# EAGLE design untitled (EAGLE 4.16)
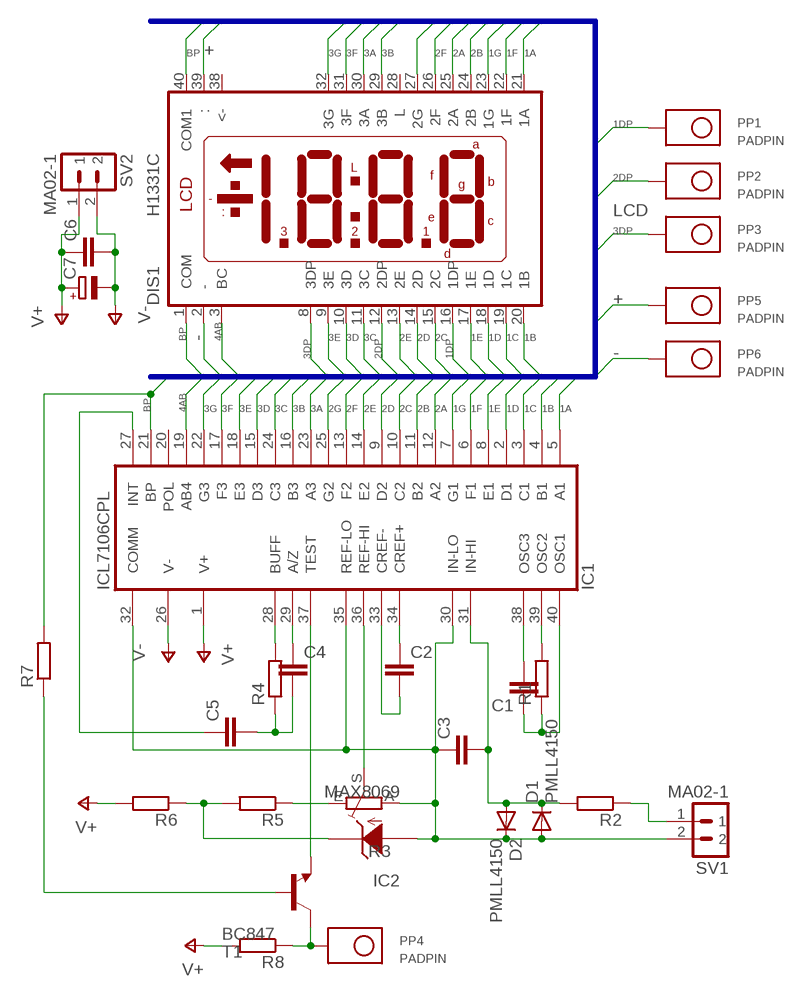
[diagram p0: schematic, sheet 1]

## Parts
C1  C-EUC1210  [C1210]
C2  C-EUC1210  [C1210]
C3  C-EUC1210  [C1210]
C4  C-EUC1210  [C1210]
C5  C-EUC1210  [C1210]
C6  C-EUC1210  [C1210]
C7  CPOL-EUE2.5-5  [E2,5-5]
D1  PMLL4150  [SOD80C]
D2  PMLL4150  [SOD80C]
DIS1  H1331C  [H1331C]
IC1  ICL7106CPL  [DIL40]
IC2  MAX8069  [TO92-2]
PP1  PADPIN  [PAD]
PP2  PADPIN  [PAD]
PP3  PADPIN  [PAD]
PP4  PADPIN  [PAD]
PP5  PADPIN  [PAD]
PP6  PADPIN  [PAD]
R1  R-EU_M1206  [M1206]
R2  R-EU_M1206  [M1206]
R3  TRIM_EU-B90P  [SP19L]
R4  R-EU_M1206  [M1206]
R5  R-EU_M1206  [M1206]
R6  R-EU_M1206  [M1206]
R7  R-EU_M1206  [M1206]
R8  R-EU_M1206  [M1206]
SV1  MA02-1  [MA02-1]
SV2  MA02-1  [MA02-1]
T1  BC847  [SOT23]

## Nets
1A: DIS1.21(1A) IC1.5(A1)
1B: DIS1.20(1B) IC1.4(B1)
1C: DIS1.19(1C) IC1.3(C1)
1D: DIS1.18(1D) IC1.2(D1)
1DP: DIS1.16(1DP) PP1.P$1
1E: DIS1.17(1E) IC1.8(E1)
1F: DIS1.22(1F) IC1.6(F1)
1G: DIS1.23(1G) IC1.7(G1)
2A: DIS1.25(2A) IC1.12(A2)
2B: DIS1.24(2B) IC1.11(B2)
2C: DIS1.15(2C) IC1.10(C2)
2D: DIS1.14(2D) IC1.9(D2)
2DP: DIS1.12(2DP) PP2.P$1
2E: DIS1.13(2E) IC1.14(E2)
2F: DIS1.26(2F) IC1.13(F2)
2G: DIS1.27(2G) IC1.25(G2)
3A: DIS1.30(3A) IC1.23(A3)
3B: DIS1.29(3B) IC1.16(B3)
3C: DIS1.11(3C) IC1.24(C3)
3D: DIS1.10(3D) IC1.15(D3)
3DP: DIS1.8(3DP) PP3.P$1
3E: DIS1.9(3E) IC1.18(E3)
3F: DIS1.31(3F) IC1.17(F3)
3G: DIS1.32(3G) IC1.22(G3)
4AB: DIS1.3(BC) IC1.19(AB4)
+: DIS1.39(:) PP5.P$1
-: DIS1.2(-) PP6.P$1
BP: DIS1.1(COM) DIS1.40(COM1) IC1.21(BP) R7.2
N$1: IC1.39(OSC2) R1.2
N$2: C1.2 IC1.38(OSC3)
N$3: C1.1 IC1.40(OSC1) R1.1
N$4: C3.2 D1.C D2.A IC1.31(IN-HI) R2.2
N$5: IC1.36(REF-HI) R3.S
N$6: R2.1 SV1.1
N$7: C2.2 IC1.33(CREF-)
N$8: C2.1 IC1.34(CREF+)
N$9: C3.1 D1.A D2.C IC1.30(IN-LO) IC1.32(COMM) IC1.35(REF-LO) IC2.A R3.A SV1.2
N$10: C4.1 IC1.29(A/Z)
N$11: IC1.28(BUFF) R4.2
N$12: C5.1 IC1.27(INT)
N$13: C4.2 C5.2 R4.1
N$14: R3.E R5.1
N$15: IC2.K R5.2 R6.1
N$16: R7.1 T1.1(B)
N$17: IC1.37(TEST) T1.2(E)
N$18: PP4.P$1 R8.1 T1.3(C)
V+: C6.1 C7.+ IC1.1(V+) R6.2 R8.2 SV2.1
V-: C6.2 C7.- IC1.26(V-) SV2.2
Unconnected: DIS1.28(L) DIS1.38(<-) IC1.20(POL)

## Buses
LCD

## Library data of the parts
C1-C6 = rcl:C-EU: CAPACITOR, European symbol
C7 = rcl:CPOL-EU: POLARIZED CAPACITOR, European symbol
D1 D2 = diode:PMLL4150: DIODE
DIS1 = display-lcd:H1331C: LCD DISPLAY 3 1/2 character 7 segment
IC1 = maxim:ICL7106CPL: LCD DRIVER
IC2 = max8069:MAX8069
PP1-PP6 = pady:PADPIN
R1 R2 R4-R8 = rcl:R-EU_: RESISTOR, European symbol
R3 = pot:TRIM_EU-: POTENTIOMETER
SV1 SV2 = divers:MA02-1: PIN HEADER
T1 = transistor:BC847: NPN TRANSISTOR

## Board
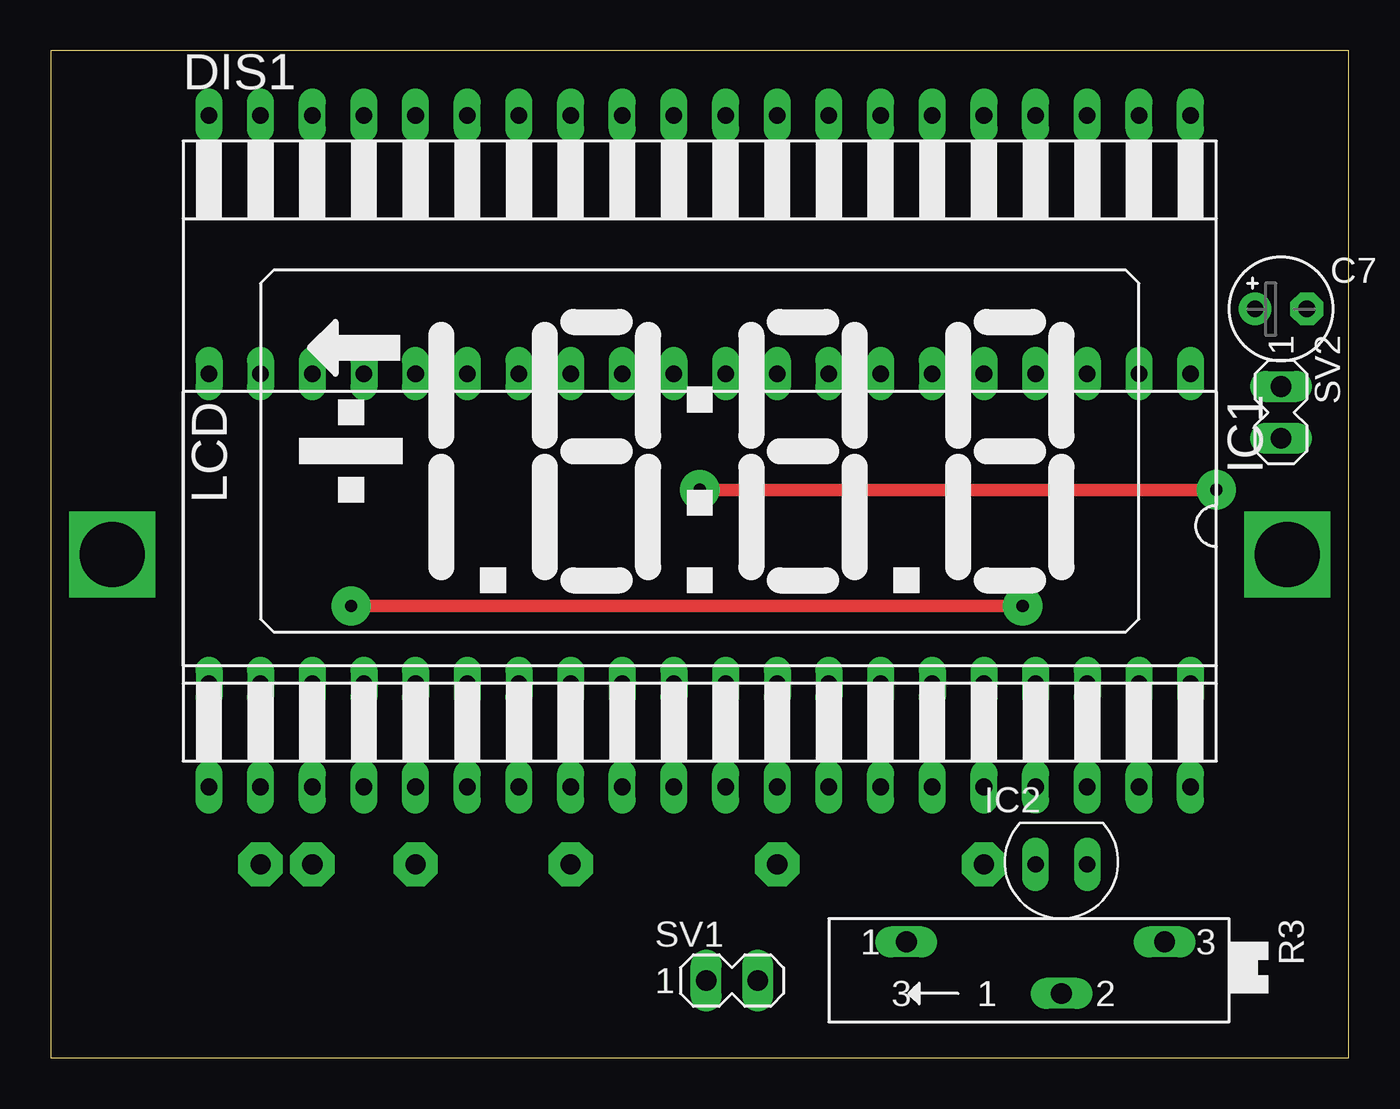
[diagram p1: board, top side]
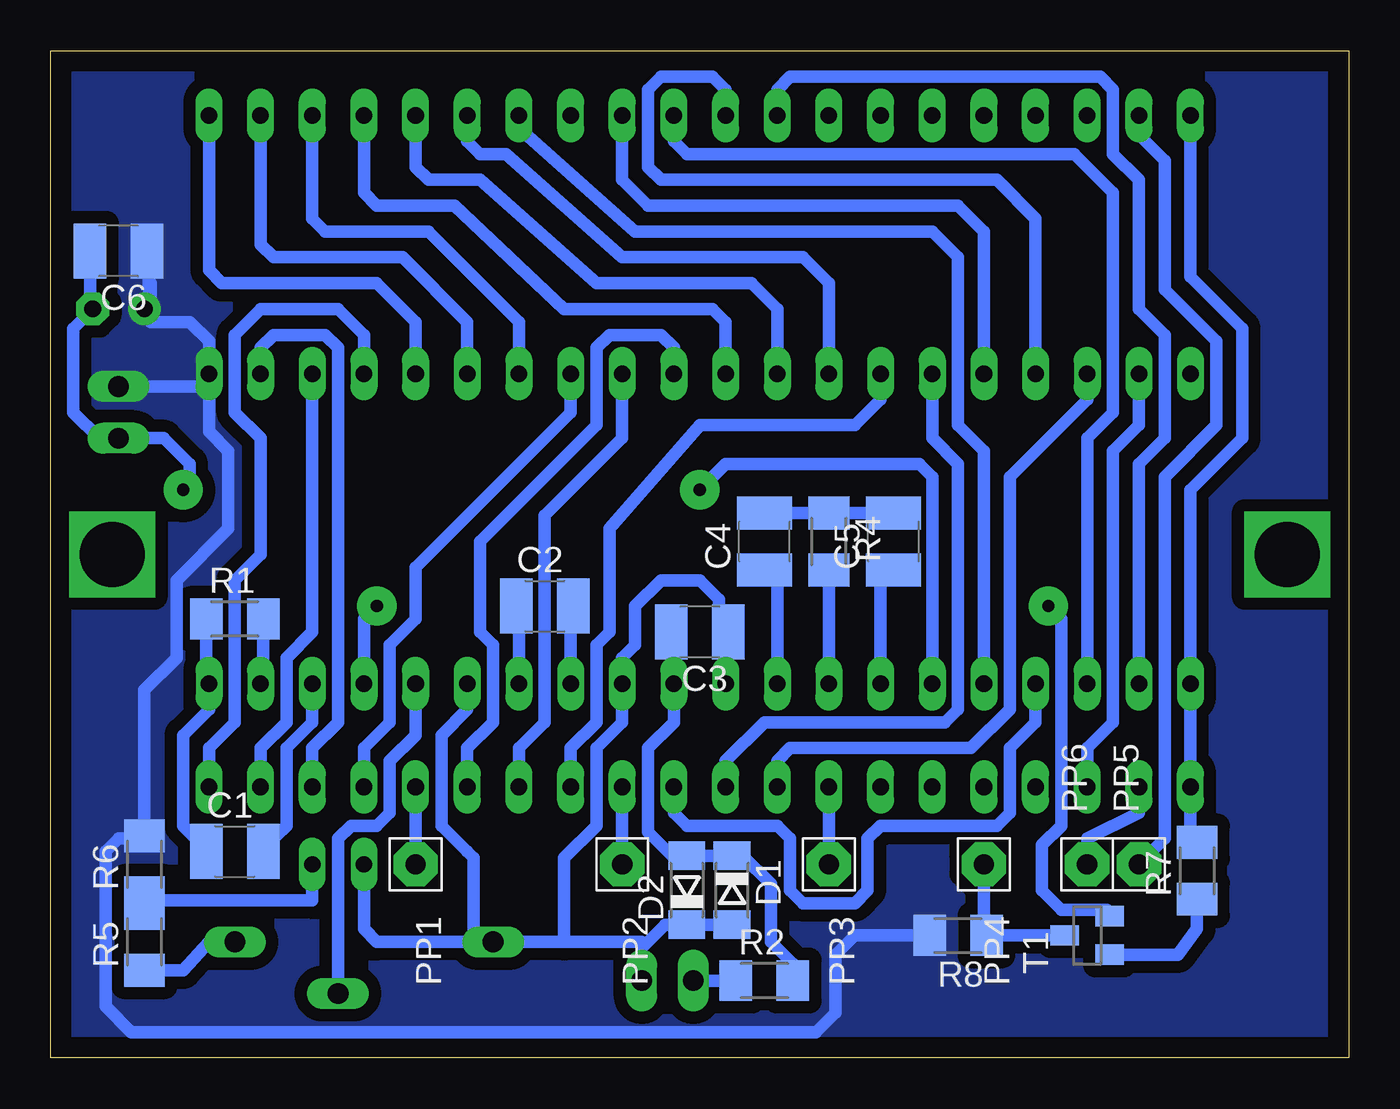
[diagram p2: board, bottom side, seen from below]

Size 63.8 x 49.52 mm. Coordinates in mm from the lower left corner, seen from the top.
Outline: 0,0 63.8,0 63.8,49.52 0,49.52 0,0
Copper layers (1*16): Top 0.035mm / dielectric 1.5mm / Bottom 0.035mm
Design rules "default": minimum track width 10mil, minimum drill 24mil, track to track 8mil, track to pad 8mil, pad to pad 8mil, via to via 8mil, smd to smd 8mil, copper to edge 40mil, drill to drill 8mil, minimum pad ring 10mil, minimum via ring 8mil, stop-mask expansion 4mil, vias tented up to drill 0mil, thermal gap 10mil

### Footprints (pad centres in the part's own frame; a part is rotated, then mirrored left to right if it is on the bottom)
C1210 = smd 1.6 x 2.7: 1 -1.4,0; 2 1.4,0
E2,5-5 = drill 0.813 pad 1.6 round: + -1.27,0 | drill 0.813 pad 1.6 octagon: - 1.27,0
SOD80C = smd 1.4 x 1.8: A 1.7,0; C -1.7,0
H1331C = drill 0.813 long: 1 -24.13,-16.51; 2 -21.59,-16.51; 3 -19.05,-16.51; 4 -16.51,-16.51; 5 -13.97,-16.51; 6 -11.43,-16.51; 7 -8.89,-16.51; 8 -6.35,-16.51; 9 -3.81,-16.51; 10 -1.27,-16.51; 11 1.27,-16.51; 12 3.81,-16.51; 13 6.35,-16.51; 14 8.89,-16.51; 15 11.43,-16.51; 16 13.97,-16.51; 17 16.51,-16.51; 18 19.05,-16.51; 19 21.59,-16.51; 20 24.13,-16.51; 21 24.13,16.51; 22 21.59,16.51; 23 19.05,16.51; 24 16.51,16.51; 25 13.97,16.51; 26 11.43,16.51; 27 8.89,16.51; 28 6.35,16.51; 29 3.81,16.51; 30 1.27,16.51; 31 -1.27,16.51; 32 -3.81,16.51; 33 -6.35,16.51; 34 -8.89,16.51; 35 -11.43,16.51; 36 -13.97,16.51; 37 -16.51,16.51; 38 -19.05,16.51; 39 -21.59,16.51; 40 -24.13,16.51
DIL40 = drill 0.813 long: 1 -24.13,-7.62; 2 -21.59,-7.62; 3 -19.05,-7.62; 4 -16.51,-7.62; 5 -13.97,-7.62; 6 -11.43,-7.62; 7 -8.89,-7.62; 8 -6.35,-7.62; 9 -3.81,-7.62; 10 -1.27,-7.62; 11 1.27,-7.62; 12 3.81,-7.62; 13 6.35,-7.62; 14 8.89,-7.62; 15 11.43,-7.62; 16 13.97,-7.62; 17 16.51,-7.62; 18 19.05,-7.62; 19 21.59,-7.62; 20 24.13,-7.62; 21 24.13,7.62; 22 21.59,7.62; 23 19.05,7.62; 24 16.51,7.62; 25 13.97,7.62; 26 11.43,7.62; 27 8.89,7.62; 28 6.35,7.62; 29 3.81,7.62; 30 1.27,7.62; 31 -1.27,7.62; 32 -3.81,7.62; 33 -6.35,7.62; 34 -8.89,7.62; 35 -11.43,7.62; 36 -13.97,7.62; 37 -16.51,7.62; 38 -19.05,7.62; 39 -21.59,7.62; 40 -24.13,7.62
TO92-2 = drill 0.8 long: A 0,0; K 0,2.54
PAD = drill 1 pad 2.184 octagon: P$1 0,0
M1206 = smd 1.6 x 2: 1 -1.4,0; 2 1.4,0
SP19L = drill 1.016 long: A 5.715,-1.27; E -6.985,-1.27; S -1.905,1.27
MA02-1 = drill 1.016 long: 1 -2.54,0; 2 0,0
SOT23 = smd 1 x 1.4: 1 -0.95,-1.1; 2 0.95,-1.1; 3 0,1.1

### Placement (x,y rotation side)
C1  54.76,10.15 0 bottom
C2  39.52,22.22 0 bottom
C3  31.9,20.95 180 bottom
C4  28.73,25.39 90 bottom
C5  22.38,25.39 90 bottom
C6  60.48,39.68 180 bottom
C7  60.48,36.82 0 top
D1  30.31,8.25 270 bottom
D2  32.54,8.25 90 bottom
DIS1  31.9,29.84 0 top
IC1  31.9,26.03 180 top
IC2  48.41,9.52 270 top
PP1  45.87,9.52 180 bottom
PP2  35.71,9.52 180 bottom
PP3  25.55,9.52 180 bottom
PP4  17.93,9.52 180 bottom
PP5  10.31,9.52 0 bottom
PP6  12.85,9.52 0 bottom
R1  54.76,21.59 0 bottom
R2  28.73,3.8 0 bottom
R3  47.78,4.44 180 top
R4  25.55,25.39 270 bottom
R5  59.21,5.71 90 bottom
R6  59.21,9.52 90 bottom
R7  7.46,9.2 90 bottom
R8  19.2,6.03 180 bottom
SV1  34.76,3.8 0 top
SV2  60.48,30.47 270 top
T1  12.85,6.03 90 bottom

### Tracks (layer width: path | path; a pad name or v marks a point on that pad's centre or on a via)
1A
  Bottom 0.61: IC1.5 45.87,36.19 47.78,38.09 55.4,38.09 56.03,38.73 DIS1.21
1B
  Bottom 0.61: IC1.4 48.41,35.55 49.68,36.82 53.49,36.82 54.76,35.55 54.76,31.74 53.49,30.47 53.49,24.76 54.76,23.49 54.76,16.51 56.03,15.24 DIS1.20
1C
  Bottom 0.61: IC1.3 50.95,20.95 52.22,19.68 52.22,16.51 53.49,15.24 DIS1.19
1D
  Bottom 0.61: DIS1.18 50.95,15.24 49.68,16.51 49.68,34.92 50.32,35.55 52.86,35.55 53.49,34.92 IC1.2
1DP
  Bottom 0.61: PP1.P$1 DIS1.16
1E
  Bottom 0.61: IC1.8 38.25,31.74 45.87,24.12 45.87,21.59 47.14,20.31 47.14,16.51 48.41,15.24 DIS1.17
1F
  Bottom 0.61: IC1.6 43.33,36.19 46.51,39.36 52.86,39.36 53.49,40 DIS1.22
1G
  Bottom 0.61: IC1.7 40.79,36.19 45.24,40.63 50.32,40.63 50.95,41.27 DIS1.23
2A
  Bottom 0.61: IC1.12 28.09,36.82 29.36,38.09 36.98,38.09 42.7,43.17 45.24,43.17 45.87,43.81 DIS1.25
2B
  Bottom 0.61: IC1.11 30.63,36.19 31.27,36.82 38.57,36.82 43.97,41.91 47.78,41.91 48.41,42.54 DIS1.24
2C
  Bottom 0.61: IC1.10 33.17,34.92 33.81,35.55 36.35,35.55 36.98,34.92 36.98,31.11 42.7,25.39 42.7,20.95 42.06,20.31 42.06,16.51 43.33,15.24 DIS1.15
2D
  Bottom 0.61: IC1.9 35.71,30.47 39.52,26.66 39.52,16.51 40.79,15.24 DIS1.14
2DP
  Bottom 0.61: PP2.P$1 DIS1.12
2E
  Bottom 0.61: IC1.14 23.01,32.38 24.28,31.11 31.9,31.11 36.35,26.03 36.35,20.95 36.98,20.31 36.98,16.51 38.25,15.24 DIS1.13
2F
  Bottom 0.61: IC1.13 25.55,38.09 26.82,39.36 35.71,39.36 41.43,44.45 42.7,44.45 43.33,45.08 DIS1.26
2G
  Bottom 0.61: IC1.25 17.93,29.84 19.2,31.11 19.2,39.36 20.47,40.63 35.08,40.63 40.79,45.71 DIS1.27
3A
  Bottom 0.61: IC1.23 12.85,30.47 11.58,31.74 11.58,42.54 13.49,44.45 32.54,44.45 33.17,45.08 DIS1.30
3B
  Bottom 0.61: DIS1.29 35.71,43.17 34.44,41.91 19.2,41.91 17.93,40.63 IC1.16
3C
  Bottom 0.61: IC1.24 15.39,16.51 16.66,15.24 16.66,12.06 17.3,11.42 23.01,11.42 23.65,10.79 23.65,8.25 24.28,7.62 26.82,7.62 27.46,8.25 27.46,10.79 28.09,11.42 32.54,11.42 33.17,12.06 DIS1.11
3D
  Bottom 0.61: IC1.15 20.47,30.47 19.2,29.2 19.2,17.14 19.84,16.51 28.73,16.51 30.63,14.6 DIS1.10
3DP
  Bottom 0.61: PP3.P$1 DIS1.8
3E
  Bottom 0.61: IC1.18 12.85,32.38 16.66,28.57 16.66,17.14 18.57,15.24 27.46,15.24 28.09,14.6 DIS1.9
3F
  Bottom 0.61: DIS1.31 30.63,47.62 31.27,48.25 33.81,48.25 34.44,47.62 34.44,43.81 33.81,43.17 17.3,43.17 15.39,41.27 IC1.17
3G
  Bottom 0.61: IC1.22 10.31,29.2 9.04,30.47 9.04,35.55 10.31,36.82 10.31,43.17 11.58,44.45 11.58,47.62 12.22,48.25 27.46,48.25 28.09,47.62 DIS1.32
4AB
  Bottom 0.61: DIS1.3 12.85,15.24 11.58,16.51 11.58,29.84 10.31,31.11 IC1.19
+
  Bottom 0.61: DIS1.39 10.31,45.4 9.04,44.13 9.04,37.78 6.5,35.24 6.5,31.11 9.04,28.57 9.04,13.65 | 9.04,13.65 9.04,13.33 | PP5.P$1 9.04,10.79 9.04,13.65
-
  Bottom 0.61: DIS1.2 10.31,12.06 12.85,10.79 PP6.P$1
BP
  Bottom 0.61: DIS1.40 7.77,38.41 5.23,35.87 5.23,30.47 7.77,27.93 IC1.21 DIS1.1 7.77,10.79 R7.2
N$1
  Bottom 0.61: R1.2 53.36,18.54 IC1.39
N$2
  Bottom 0.61: IC1.38 50.95,16.51 52.22,15.24 52.22,11.42 52.73,10.92 C1.2
N$3
  Bottom 0.61: R1.1 56.16,18.54 IC1.40 56.03,17.14 57.3,15.87 57.3,11.42 56.03,10.15 C1.1
N$4
  Bottom 0.406: 32.54,9.84 32.54,9.52 | D1.C 30.31,9.52
  Bottom 0.61: C3.2 33.17,20.95 IC1.31 33.17,16.51 34.44,15.24 34.44,11.11 33.17,9.84 32.54,9.84 | R2.2 27.33,4.63 28.41,5.71 28.41,8.57 29.79,9.95 D1.C 32.42,9.95 32.54,9.84 | 32.54,9.84 D2.A
N$5
  Bottom 0.61: IC1.36 45.87,15.87 47.14,14.6 47.14,12.06 47.78,11.42 49.05,11.42 49.68,10.79 R3.S
N$6
  Bottom 0.61: R2.1 SV1.1
N$7
  Bottom 0.61: C2.2 38.25,22.22 IC1.33
N$8
  Bottom 0.61: C2.1 40.79,22.22 IC1.34
N$9
  Bottom 0.61: C3.1 30.5,20.45 30.63,19.68 IC1.30 | 30.31,20.95 30,20.95 | C3.1 30.95,20.95 | IC1.35 43.33,17.14 44.6,15.87 44.6,11.42 | 44.6,11.42 43.33,10.15 | IC2.A 48.41,6.35 47.78,5.71 43.02,5.71 | 43.02,5.71 R3.A 38.57,5.71 | 34.76,5.39 34.76,5.71 38.57,5.71 | 38.57,5.71 38.57,9.84 36.98,11.42 36.98,15.24 35.71,16.51 IC1.32 35.71,19.68 35.08,20.31 35.08,22.22 33.81,23.49 31.9,23.49 30.95,22.54 30.95,21.59 30.31,20.95 | 44.6,11.42 43.02,9.84 43.02,5.71 | 30.31,20.95 C3.1 | D2.C D1.A | D2.C 32.54,6.66 | 34.76,5.39 SV1.2 | D2.C 33.6,6.55 34.76,5.39
N$10
  Bottom 0.61: C4.1 28.09,23.99 IC1.29
N$11
  Bottom 0.61: IC1.28 R4.2
N$12
  Bottom 0.61: C5.1 23.01,23.99 IC1.27
N$13
  Bottom 0.61: C5.2 R4.1 | R4.1 C4.2 | R4.1 25.55,26.66
N$14
  Bottom 0.61: R5.1 57.3,4.31 56.03,5.71 R3.E
N$15
  Bottom 0.61: 59.21,8.25 R6.1 59.21,7.74 | 59.21,7.74 50.95,7.74 IC2.K | 59.21,7.74 R5.2
N$16
  Bottom 0.61: T1.1 9.04,5.08 8.41,5.08 7.46,6.35 R7.1
N$17  (via drill 0.6 pad 1.93)
  Top 0.61: v14.76,22.22 v47.78,22.22
  Bottom 0.61: IC1.37 48.41,21.59 v47.78,22.22 | v14.76,22.22 14.12,21.59 14.12,11.42 15.08,10.47 15.08,8.25 14.12,7.29 11.9,7.29 11.58,6.98 T1.2
N$18
  Bottom 0.61: T1.3 R8.1 17.93,6.35 PP4.P$1
N$20  (via drill 3.2 pad 3.81)
  other vias: 3.01,24.76
N$21  (via drill 3.2 pad 3.81)
  other vias: 60.8,24.76
V+
  Bottom 0.61: 56.03,33.02 56.03,30.79 55.08,29.84 55.08,26.03 57.62,23.49 57.62,19.68 59.21,18.09 R6.2 59.21,10.79 60.48,10.79 61.11,10.15 61.11,2.54 59.84,1.26 26.19,1.26 25.23,2.22 25.23,5.08 24.28,6.03 R8.2 | 56.03,33.02 IC1.1 56.03,35.24 56.98,36.19 58.89,36.19 | 56.03,33.02 55.72,33.02 | 56.03,33.02 SV2.1 | 58.89,36.19 C6.1 | 58.89,36.19 58.89,38.09
  pour Bottom (isolate 0.61, no thermals): -0.8,50.16 64.61,50.16 64.92,-0.64 -0.48,-0.64
V-  (via drill 0.6 pad 1.93)
  Top 0.61: v31.9,27.93 v57.3,27.93
  Bottom 0.61: v57.3,27.93 56.98,28.25 56.98,29.2 58.25,30.47 61.43,30.47 | IC1.26 20.47,28.57 21.11,29.2 30.63,29.2 v31.9,27.93 | 61.43,30.47 62.7,31.74 62.7,35.87 C7.- 62.06,36.82 61.88,37.01 C6.2 | 61.43,30.47 SV2.2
